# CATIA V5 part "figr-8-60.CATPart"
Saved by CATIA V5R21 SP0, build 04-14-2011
Part number: Part1
Bounding box of the stored display mesh (mm): x -50.499 to 50.499, y -68.48 to 68.48, z 0 to 20
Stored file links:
  D:\CATIA V5R21 E-RESOURCES\CATIA-V5R21\catia-v5r21-prt\c08-catia-v5r20-prt\c08-catia-v5r21-figr-8-60.CATPart
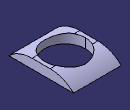
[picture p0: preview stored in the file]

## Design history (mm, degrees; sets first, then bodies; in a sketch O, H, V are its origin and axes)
Body1 (main body)
  Sketch1 on xy-plane, origin (0, 0, 0), H (1, 0, 0), V (0, 1, 0)
    line L1 (-50.499, 68.4797) -> (50.499, 68.4797)
    line L2 (50.499, 68.4797) -> (50.499, -68.4797)
    line L3 (50.499, -68.4797) -> (-50.499, -68.4797)
    line L4 (-50.499, -68.4797) -> (-50.499, 68.4797)
    axis line L5 (50.499, -68.4797) -> (-50.499, 68.4797)
    horizontal: L1 H, L3 H
    vertical: L2 V, L4 V
    midpoint: O L5
  Pad1: profile Sketch1, direction (0, 0, 1), length 20
  Fillet1: radius 71, on edge [face of Pad1 | face of Pad1]
  Fillet2: radius 71, on edge [face of Pad1 | face of Pad1]
  Body2
    Sketch2 on xy-plane, origin (0, 0, 0), H (1, 0, 0), V (0, 1, 0)
      circle A1 centre (0, 0) radius 43.2524
      point P1 (0, 43.2524)
      coincidence: A1 P1, P1 V
    Pocket1: profile Sketch2, direction (0, 0, -1), length 50, mirrored extent
  Assemble1: tool Body2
